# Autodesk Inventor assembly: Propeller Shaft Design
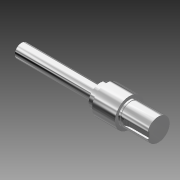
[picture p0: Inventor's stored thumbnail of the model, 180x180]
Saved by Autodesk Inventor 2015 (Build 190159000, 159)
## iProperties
Created: 2007-02
Part Number: Propeller Shaft Design
Document SubType Name: Assembly
Designer: Autodesk, Inc.
Mass: 3342.5 g
Surface Area: 452.362 cm^2
Volume: 425.796 cm^3
Density: 7.85 g/cm^3
ClientObjectVersion: 1
Author: Autodesk, Inc.
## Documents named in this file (2)
- C:\Users\Public\Documents\Autodesk\Inventor 2015\Samples\Models\Assemblies\Blower\Blower\Design Accelerator\Shaft1.iam
- C:\Users\Public\Documents\Autodesk\Inventor 2015\Samples\Models\Assemblies\Blower\Blower\Design Accelerator\Shaft1.ipt
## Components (1 placed, 1 different names)
1. SH - 0001 :1
